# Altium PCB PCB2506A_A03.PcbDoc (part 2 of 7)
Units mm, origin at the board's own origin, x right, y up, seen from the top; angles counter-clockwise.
Board outline 115 x 60 mm, 6 copper layers (Top Layer, Signal Layer 2, Signal Layer 3, Signal Layer 4, Signal Layer 5, Bottom Layer), stack 1.555 mm thick; 376 components, 290 nets, 1297 pads, 901 vias.
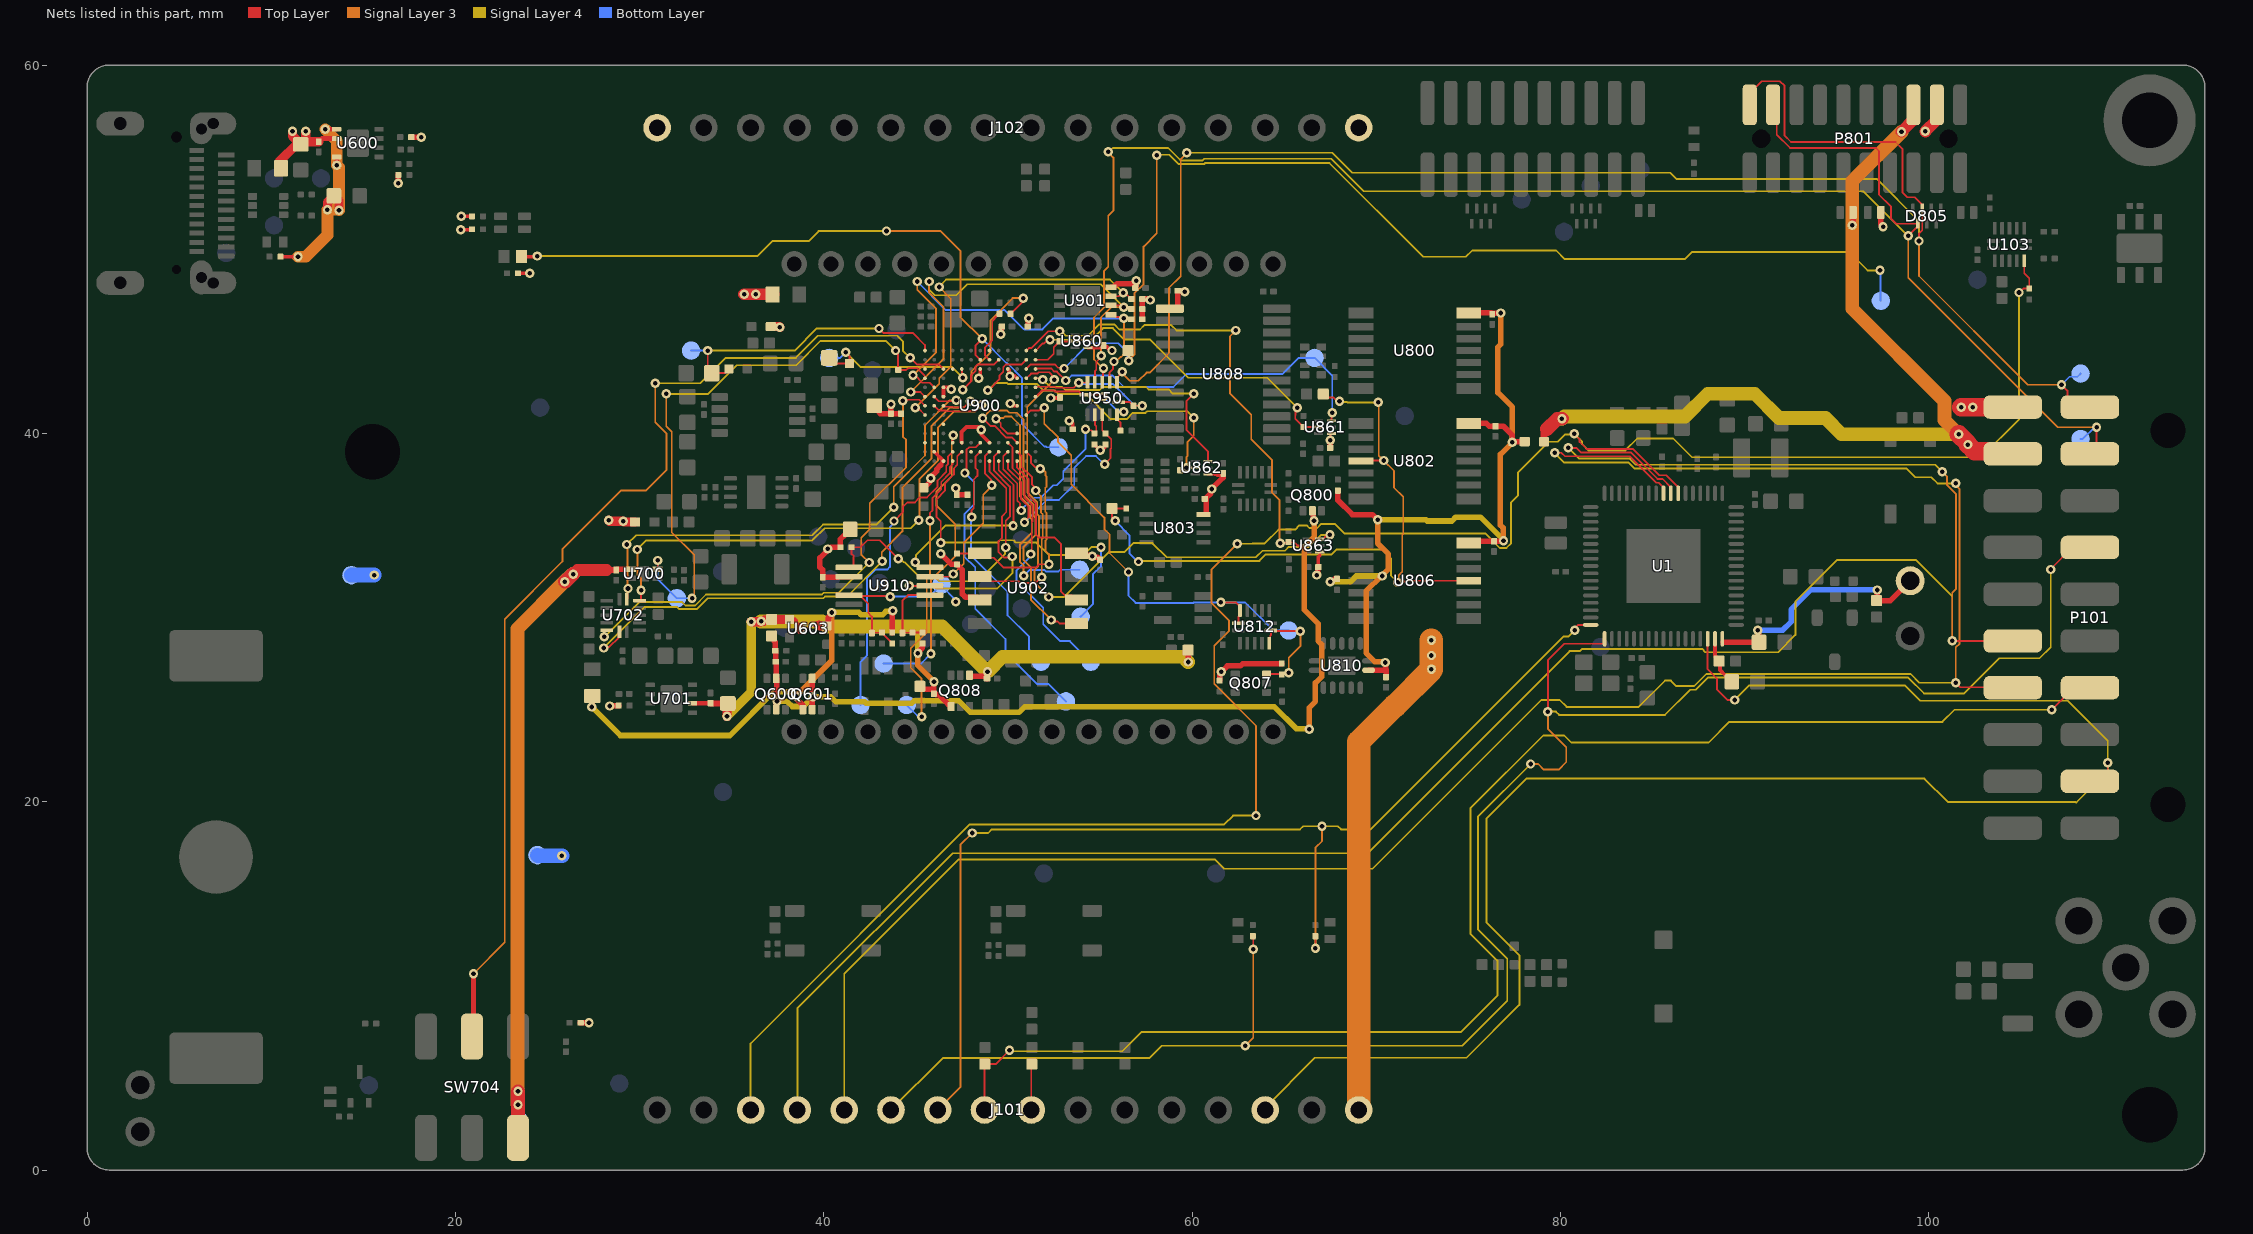
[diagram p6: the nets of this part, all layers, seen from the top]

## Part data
LED900: library part Yellow
LED901: library part Blue

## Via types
v1: diameter 0.508, hole 0.25, Top Layer to Bottom Layer, tented both sides, 901 vias

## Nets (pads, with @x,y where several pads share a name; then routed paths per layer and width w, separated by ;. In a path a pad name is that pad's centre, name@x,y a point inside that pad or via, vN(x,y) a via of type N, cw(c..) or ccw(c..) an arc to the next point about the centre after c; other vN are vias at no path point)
3V3: C607.1 C807.1 C808.1 C860.1 C862.1 C864.1 C866.1 C907.1 C908.1 C909.1 C910.1 C911.1 C914.1 C921.1 C922.1 C924.1 C925.1 C926.1 C927.1 C951.1 D807.1 J101.16 J102.16 L704.1 L900.1 P101.20 P801.3 R601.2 R793.2 R838.2 R840.2 R903.1 R906.2 R907.1 R908.1 R909.1 R912.1 R919.1 R920.1 R951.1 R952.1 R982.1 TPJ600.1 TPJ950.1 U600.1 U600.4 U803.8 U808.1 U860.1 U861.1 U862.1 U863.1 U900.C6 U900.C9 U900.G3 U900.H11 U900.J11 U900.K3 U900.L4 U900.L7 U901.8 U902.3 U902.8 U910.2 | length 92.6
  Top Layer w0.1: v1(67.513,39.624) 67.513,39.968 67.538,39.993 U861.1@67.573,39.993
  Top Layer w0.15: U862.1@60.873,37.785 61.239,37.785 ; 66.936,33.373 U863.1@66.936,33.563
  Top Layer w0.2: R903.1@10.5,49.6 v1(11.45,49.6) ; v1(20.295,51.054) R919.1@20.901,51.054 ; v1(20.32,51.791) 20.852,51.791 20.877,51.765 R920.1@20.901,51.789 ; R912.1@23.401,48.7 23.418,48.717 23.444,48.692 v1(24.028,48.692) ; U900.H11@46.5,42 U900.J11@46.5,42.5 46.825,42.5 v1(46.925,42.4) ; U900.C9@47.5,39.5 47.482,39.518 47.482,40.083 47.749,40.35 48.425,40.35 48.55,40.225 v1@48.55,40.075 ; v1(48.425,43) 48.45,43 48.5,43.05 U900.L7@48.5,43.5 ; v1(48.55,40.2) v1@48.55,40.075 ; U900.C6@49,39.5 48.525,39.975 48.55,40 v1@48.55,40.075 ; U900.L4@50,43.5 50.058,43.442 50.058,43.165 v1(50.112,43.112) ; v1(50.125,41.625) 50.25,41.5 U900.G3@50.5,41.5 ; v1@50.125,43.125 50.375,43.125 U900.K3@50.5,43 ; v1(52.325,41.925) 52.325,41.9 52.4,41.825 52.5,41.925 C911.1@52.825,41.925 ; v1(53.336,40.692) 53.336,40.714 53.325,40.725 53.35,40.725 53.525,40.55 C909.1@53.525,40.225 ; U860.1@54.35,44.65 55.023,44.65 55.068,44.695 55.14,44.695 C862.1@55.2,44.755 ; R951.1@54.7,39.4 54.7,39.39 54.94,39.15 v1@55.051,39.15 ; v1(55.021,39.091) 55.079,39.15 55.178,39.15 55.26,39.233 55.26,39.36 R952.1@55.3,39.4 ; C862.1@55.2,44.775 C862.1@55.2,44.755 ; v1(55.651,44.502) 55.573,44.502 55.38,44.695 55.26,44.695 C862.1@55.2,44.755 ; 61.239,37.785 61.392,37.785 ; C866.1@66.857,32.745 66.857,33.294 66.936,33.373
  Top Layer w0.25: v1@13.038,56.513 U600.1@13.55,56.513 ; U600.4@13.55,55.013 13.557,55.013 13.557,54.566 v1(13.564,54.559)
  Top Layer w0.3: v1(12.929,56.515) 13.036,56.515 v1@13.038,56.513 ; v1(16.891,53.594) 16.896,53.599 16.896,54.031 R601.2@16.9,54.035 ; R793.2@26.79,8 27.253,8 v1(27.254,8.001) ; U910.2@41.374,32.22 40.799,32.22 40.774,32.195 C922.1@39.946,32.195 39.936,32.205 39.936,32.595 39.794,32.737 39.794,33.239 40.226,33.671 v1(40.226,33.727) 40.282,33.727 40.376,33.821 R982.1@40.906,33.821 40.906,34.265 41.082,34.44 41.107,34.44 41.434,34.767 C921.1@41.434,34.792 ; C907.1@42.75,41.4 43.075,41.075 C924.1@43.65,41.075 ; v1(43.65,41.575) C924.1@43.65,41.075 ; C925.1@44.2,41.075 C924.1@43.65,41.075 ; v1@46.33,33.435 v1(46.357,33.463) 46.918,32.902 47.234,32.902 47.244,32.892 R906.2@47.244,32.882 47.244,32.872 47.531,32.585 47.531,31.28 47.707,31.104 48.322,31.104 U902.3@48.472,30.954 ; v1(47.175,37.033) 47.175,36.977 47.215,36.937 47.215,36.685 C927.1@47.225,36.675 C926.1@47.808,36.675 ; v1(49.612,45.383) 49.645,45.416 C910.1@49.645,45.757 ; C908.1@51.075,45.8 51.093,45.8 51.103,45.81 51.103,46.226 v1(51.13,46.253) ; v1(54.585,33.325) 54.624,33.285 54.866,33.285 54.983,33.169 55.003,33.169 55.013,33.159 C914.1@55.013,33.139 ; U901.8@55.6,47.95 55.75,47.95 55.933,48.133 56.842,48.133 C951.1@56.958,48.017 ; R908.1@57.3,46.2 R907.1@57.3,46.75 R909.1@57.3,47.3 57.622,47.3 57.678,47.244 v1(57.734,47.244) ; U808.1@58.8,46.775 59.15,46.775 59.225,46.85 C808.1@59.225,47.75 59.235,47.74 59.51,47.74 59.518,47.732 59.574,47.732 v1(59.614,47.693) ; C807.1@60.725,36.455 v1@61.022,36.751 ; U803.8@60.783,35.624 C807.1@60.783,36.378 ; v1(61.062,36.982) 61.685,37.606 C860.1@61.685,37.795 ; 61.392,37.785 61.47,37.785 61.48,37.795 C860.1@61.685,37.795 ; R838.2@61.5,26.587 61.51,26.597 61.51,26.91 61.595,26.995 v1(61.595,27.051) 61.919,27.375 62.63,27.375 62.76,27.505 R840.2@64.87,27.505 ; C860.1@61.695,37.805 C860.1@61.685,37.795 ; v1(66.777,32.309) 66.777,32.365 66.827,32.415 66.827,32.735 66.837,32.745 C866.1@66.857,32.745 ; C864.1@67.5,39.214 67.503,39.214 67.513,39.224 v1(67.513,39.624) ; D807.1@97.4,52 97.4,51.35 v1(97.525,51.225)
  Top Layer w0.35: U902.8@53.722,33.494 53.847,33.369 54.498,33.369 54.542,33.325 v1(54.585,33.325)
  Top Layer w0.5: v1(13.05,52.15) 13.05,52.55 C607.1@13.4,52.9 13.675,52.625 v1(13.675,52.125) ; L704.1@37.125,45.8 37.586,45.8 37.615,45.771 v1(37.617,45.771)
  Top Layer w0.635: v1(35.675,47.55) v1(36.3,47.55) L900.1@37.225,47.55 L900.1@37.285,47.55 ; v1(99.825,56.4) 100.445,57.02 P801.3@100.445,57.841 ; v1(102.387,41.427) 102.39,41.43 P101.20@104.57,41.43
  Top Layer w1: v1(101.778,41.427) v1(102.387,41.427) 104.567,41.427 P101.20@104.57,41.43
  Signal Layer 3 w0.635: v1(11.45,49.6) 11.881,49.6 13.05,50.769 v1(13.05,52.15) 13.65,52.15 v1(13.675,52.125) 13.675,54.448 v1(13.564,54.559) 13.564,55.88 v1(12.929,56.515)
  Signal Layer 3 w1.27: J101.16@69.05,3.262 69.05,23.254 71.015,25.218 71.035,25.218 73,27.183 v1(73,27.203) v1(73,27.94) v1(73,28.778)
  Bottom Layer w0.8: TPJ600.1@14.353,32.302 14.36,32.309 v1(15.596,32.309) ; TPJ950.1@24.452,17.1 24.484,17.069 v1(25.781,17.069)
  other v1: 56.974,48.285
3V6_SW: C608.1 L702.1 Q601.1 R639.2 U603.B1 | length 26
  Top Layer w0.2: U603.B1@39.35,29.6 39.735,29.6
  Top Layer w0.3: v1(27.407,25.146) 27.419,25.159 27.419,25.743 L702.1@27.407,25.756 ; v1(38.506,25.73) 38.546,25.69 38.546,25.563 38.869,25.24 Q601.1@38.869,25.09 ; C608.1@40.169,29.55 40.235,29.616 40.235,29.991 40.397,30.153 40.397,30.337 v1@40.411,30.351 ; R639.2@43.719,29.19 43.719,30.337 v1(43.755,30.373)
  Top Layer w0.5: 39.735,29.6 39.785,29.55 C608.1@40.169,29.55
  Signal Layer 3 w0.3: v1(38.506,25.73) 40.437,27.661 v1(40.437,30.277)
  Signal Layer 4 w0.3: v1(27.407,25.146) 28.956,23.597 34.9,23.597 37.287,25.984 38.196,25.984 38.45,25.73 v1(38.506,25.73) ; v1(40.437,30.277) 41.906,30.277 42.032,30.151 43.197,30.151 43.379,30.334 43.715,30.334 v1(43.755,30.373)
3V6_SW_SENSE: C641.1 R639.1 R640.2 TP923.1 U910.4 | length 10.3
  Top Layer w0.1: U910.4@41.374,31.22 41.414,31.18 U910.4@41.989,31.18 ; v1(43.612,31.14) 43.572,31.18 U910.4@41.989,31.18 ; R639.1@43.719,28.59 43.719,28.6 43.279,29.04 43.279,29.08 R640.2@43.169,29.19 43.157,29.178 42.632,29.178 C641.1@42.619,29.165 42.619,30.054 42.418,30.255 42.418,30.751 U910.4@41.989,31.18
  Bottom Layer w0.1: v1(43.612,31.14) 45.74,31.14 TP923.1@46.4,31.8 46.4,31.714 47.168,30.947 v1(47.168,30.861)
5V: C600.1 C609.1 C611.1 C673.1 C674.1 C702.1 C703.1 C901.1 D806.1 J102.1 L600.2 L700.1 L800.1 P101.18 P801.5 Q808.1 Q808.4 R600.2 R622.2 R633.2 R681.2 R690.2 R700.2 U600.2 U603.A2 U603.B2 U701.2 U900.A11 U900.B12 | length 108.6
  Top Layer w0.2: 38.424,29.82 38.557,29.687 ; U603.A2@38.95,29.2 38.944,29.206 38.674,29.206 38.557,29.323 38.557,29.687 ; U603.B2@38.95,29.6 38.944,29.606 38.638,29.606 38.557,29.687 ; U900.B12@46,39 U900.A11@46.5,38.5 46.4,38.4 46.4,38.325 46.35,38.275
  Top Layer w0.25: C600.1@12.576,55.834 12.576,55.854 12.735,56.013 U600.2@13.55,56.013 ; U701.2@32.878,25.342 33.847,25.342 C702.1@33.858,25.354
  Top Layer w0.3: R600.2@17.651,56.083 v1(18.136,56.083) ; v1(28.372,25.197) 28.402,25.197 28.376,25.222 R700.2@28.859,25.222 ; v1(45.116,28.062) 45.116,28.118 45.359,28.362 45.359,28.57 45.369,28.58 R633.2@45.369,28.59 ; R681.2@45.216,26.27 45.366,26.12 45.97,26.12 45.97,25.878 C674.1@45.98,25.868 ; C901.1@45.45,37.05 v1@45.768,37.368 ; v1(45.808,37.564) 45.808,37.62 46.126,37.938 46.126,38.052 46.35,38.275 ; 45.986,26.12 v1(45.986,26.517) ; C674.1@46.072,25.853 46.102,25.823 46.222,25.823 46.776,25.269 46.878,25.269 Q808.1@46.878,25.111 ; Q808.4@47.878,26.822 48.707,26.822 48.843,26.687 C673.1@48.863,26.687 ; C673.1@48.883,26.687 48.878,26.692 48.878,26.96 48.893,26.975 v1(48.893,27.056) ; v1(59.785,27.585) R690.2@59.785,28.228 ; 79.116,40.076 79.273,40.234 ; v1(95.85,51.3) 95.9,51.35 D806.1@95.9,52
  Top Layer w0.35: C702.1@33.858,25.354 33.868,25.354 33.887,25.335 C703.1@34.798,25.335 ; C609.1@38.144,29.9 38.219,29.825 38.419,29.825 38.424,29.82
  Top Layer w0.4: L800.1@79.116,39.551 79.116,40.076
  Top Layer w0.5: L600.2@10.465,54.4 10.465,54.79 11.375,55.7 C611.1@11.6,55.7 ; v1(11.15,56.4) 11.15,56.15 C611.1@11.6,55.7 ; v1(11.875,56.4) 11.875,55.975 C611.1@11.734,55.834 ; C600.1@12.576,55.834 C611.1@11.734,55.834 ; v1(28.321,35.281) v1(28.321,35.281) 28.372,35.231 29.107,35.231 v1(29.108,35.23) v1(29.108,35.23) 29.145,35.195 L700.1@29.758,35.195 ; v1(34.747,24.638) 34.749,24.64 34.749,25.286 C703.1@34.798,25.335 ; v1(36.068,29.769) 36.07,29.77 36.575,29.77 36.599,29.794 v1(36.601,29.794) 36.603,29.796 36.73,29.796 36.784,29.85 37.119,29.85 R622.2@37.169,29.9 C609.1@38.144,29.9 ; C611.1@11.6,55.7 C611.1@11.734,55.834
  Top Layer w0.635: v1(98.525,56.375) 99.175,57.025 P801.5@99.175,57.841
  Top Layer w0.75: 79.273,40.234 79.832,40.792 v1(80.086,40.792) ; P101.18@104.435,39.025 P101.18@104.57,38.89
  Top Layer w1: v1(101.625,39.954) 102.133,39.446 v1(102.133,39.395) 102.504,39.025 P101.18@104.435,39.025
  Signal Layer 3 w0.3: v1(45.116,28.062) 45.116,27.401 45.986,26.531 v1(45.986,26.517)
  Signal Layer 3 w0.75: v1(98.525,56.375) 95.85,53.7 v1(95.85,51.3) 95.85,46.771 100.863,41.758 100.863,40.716 v1(101.625,39.954) 102.133,39.446 v1(102.133,39.395)
  Signal Layer 4 w0.3: v1(45.116,28.062) 45.116,29.348
  Signal Layer 4 w0.5: v1(34.747,24.638) 36.068,25.959 v1(36.068,29.769) 36.093,29.794 v1(36.601,29.794)
  Signal Layer 4 w0.75: v1(36.601,29.794) 39.904,29.794 40.184,29.515 46.434,29.515 v1(48.893,27.056) 49.708,27.871 59.5,27.871 v1(59.785,27.585) ; v1(80.086,40.792) 80.215,40.921 86.774,40.921 88.006,42.153 90.559,42.153 91.875,40.837 94.392,40.837 95.275,39.954 v1(101.625,39.954) 102.133,39.446 v1(102.133,39.395)
5V_DH_SW: C803.1 C805.1 C809.1 C827.1 L800.2 R807.1 R808.1 U800.14 U802.14 U806.14 U810.14 | length 45.4
  Top Layer w0.3: v1(67.502,31.937) 67.542,31.977 67.624,31.977 67.733,32.086 67.866,32.086 67.876,32.096 R808.1@67.876,32.106 ; R807.1@67.92,36.894 67.92,36.372 68.707,35.585 69.799,35.585 70.066,35.318 v1(70.079,35.318) ; U810.14@69.585,27.143 70.418,27.143 ; v1(70.492,27.56) 70.531,27.52 70.531,27.16 70.535,27.156 C827.1@70.535,26.768 ; U806.14@75.025,34.05 75.113,34.138 C809.1@76.402,34.138 76.402,34.145 76.412,34.155 76.895,34.155 v1(76.911,34.171) ; U802.14@75.025,40.55 75.982,40.55 76.133,40.398 76.471,40.398 C805.1@76.479,40.391 76.906,40.391 77.382,39.916 77.382,39.527 v1(77.385,39.523) 77.399,39.537 78.052,39.537 L800.2@78.066,39.551 ; U800.14@75.025,46.55 76.237,46.55 76.252,46.535 76.753,46.535 v1(76.758,46.541)
  Signal Layer 3 w0.3: v1(70.079,35.318) 70.079,34.036 70.663,33.452 70.663,32.644 70.333,32.314 v1(70.333,32.258) 70.276,32.258 69.452,31.434 69.452,28.079 69.931,27.6 70.452,27.6 v1(70.492,27.56) ; v1(76.758,46.541) 76.758,44.84 76.606,44.688 76.606,42.215 77.394,41.427 v1@77.394,39.6 ; v1(76.911,34.171) 76.889,34.193 76.889,34.875 76.739,35.025 76.739,38.864 77.394,39.519 v1@77.394,39.523
  Signal Layer 4 w0.3: v1(67.502,31.937) 68.595,31.937 68.916,32.258 v1(70.333,32.258) ; v1(70.079,35.318) 72.69,35.318 72.764,35.245 74.105,35.245 74.319,35.458 75.661,35.458 76.911,34.208 v1(76.911,34.171)
5V_SENSE: C635.1 R633.1 R634.2 U910.7 | length 4.5
  Top Layer w0.1: R633.1@45.369,29.19 R634.2@44.819,29.19 44.807,29.178 44.282,29.178 C635.1@44.269,29.165 44.269,30.909 44.581,31.22 U910.7@45.774,31.22
5V_SW: C610.1 Q600.2 Q600.5 Q601.2 Q601.5 Q800.5 R622.1 R623.2 | length 48.9
  Top Layer w0.3: R622.1@37.254,28.916 37.319,28.85 37.319,28.724 37.369,28.674 R623.2@37.369,28.2 37.372,28.2 37.382,28.19 37.382,27.61 37.392,27.6 37.409,27.6 37.419,27.59 Q600.5@37.419,26.7 37.442,26.677 37.442,25.488 v1(37.465,25.465) ; Q600.2@37.42,25.09 37.43,25.1 v1@37.43,25.481 ; Q601.2@39.369,25.09 v1@39.369,25.653 ; v1@39.369,25.516 39.381,25.528 39.381,25.665 v1(39.421,25.705) 39.369,25.756 39.381,25.768 39.381,25.801 39.369,25.813 Q601.5@39.369,26.7 ; Q800.5@66.533,35.8 66.571,35.762 66.571,35.365 66.624,35.311 v1(66.624,35.255)
  Signal Layer 3 w0.3: v1(66.37,23.927) 66.37,25.113 66.701,25.444 66.701,26.449 67.034,26.783 67.034,28.546 66.845,28.735 66.845,29.675 66.084,30.436 66.084,33.844 66.624,34.384 v1(66.624,35.255)
  Signal Layer 4 w0.3: v1(37.465,25.465) 37.478,25.452 38.014,25.452 38.294,25.171 38.887,25.171 v1(39.421,25.705) 40.379,25.705 40.658,25.426 42.222,25.426 42.303,25.345 44.769,25.345 44.904,25.48 47.337,25.48 47.965,24.852 50.599,24.852 50.918,25.171 64.458,25.171 65.666,23.963 66.334,23.963 v1(66.37,23.927)
#RESET: R805.2 R809.1 R810.2 U802.4 U806.11 | length 38.7
  Top Layer w0.1: v1(55.825,35.25) 55.65,35.425 R810.2@55.65,35.925 R809.1@56.425,35.925 ; R805.2@67.126,42.139 67.316,41.949 67.694,41.949 67.897,41.746 v1(68.008,41.746) ; U802.4@69.175,38.5 69.202,38.527 v1(70.405,38.527) ; v1(71.171,31.906) 71.215,31.95 71.575,31.95 71.625,32 U806.11@75.025,32
  Signal Layer 3 w0.1: v1(70.117,41.686) 70.142,41.66 70.142,38.79 v1(70.405,38.527) ; v1@70.417,38.514 70.968,37.963 70.968,37.059 71.467,36.559 71.467,34.555 71.414,34.502 71.414,32.497 71.226,32.31 71.226,31.961 v1(71.171,31.906)
  Signal Layer 4 w0.1: v1(57.093,33.042) 57.125,33.074 63.656,33.074 64.011,33.43 65.26,33.43 65.262,33.432 67.578,33.432 67.838,33.692 70.321,33.692 70.804,33.209 70.804,32.272 v1(71.171,31.906) ; v1(68.008,41.746) 68.048,41.706 68.412,41.706 68.432,41.686 v1(70.117,41.686)
  Bottom Layer w0.1: v1(55.825,35.25) 56.6,34.475 56.6,33.5 57.058,33.042 v1(57.093,33.042)
ADC_SMA_IN: C130.1 R129.2 U1.33 | length 2.7
  Top Layer w0.2: U1.33@88.4,28.85 88.4,27.955 88.423,27.931 88.423,27.838 88.669,27.592 88.669,27.155 88.984,26.84 89.009,26.84 89.309,26.54 C130.1@89.309,26.515
ADC_VREF: C117.1 R116.1 TPH101.1 U1.34 | length 13.5
  Top Layer w0.1: U1.34@88.798,29.007 88.8,29.005 U1.34@88.8,28.85 88.8,28.715 U1.34@88.846,28.668
  Top Layer w0.3: U1.34@88.846,28.668 90.692,28.668 C117.1@90.791,28.668 ; C117.1@90.692,28.798 90.76,28.866 90.76,29.28 v1(90.729,29.312) ; v1(97.2,31.5) 97.2,30.95 R116.1@97.175,30.925 97.925,30.925 TPH101.1@99,32
  Bottom Layer w0.3: v1(90.729,29.312) 92.07,29.312 92.528,29.77 92.528,30.438 93.59,31.5 v1(97.2,31.5)
ADC_VREF_ENABLE: J101.3 R112.1 U1.58 U103.5 | length 119.7
  Top Layer w0.1: v1(80.755,39.975) 81.04,39.689 81.04,39.542 81.42,39.162 83.93,39.162 85.366,37.725 85.75,37.725 86.4,37.075 U1.58@86.4,36.75 ; v1(104.909,47.655) 104.937,47.655 105.156,47.874 R112.1@105.461,47.874 105.461,48.415 105.188,48.688 U103.5@105.188,49.366
  Signal Layer 3 w0.1: v1(62.459,34.011) 61.062,32.614 61.062,30.776 62.013,29.824 62.013,29.273 61.202,28.462 61.202,26.403 63.475,24.13 v1(63.475,19.249)
  Signal Layer 4 w0.1: J101.3@36.03,3.262 36.03,6.871 47.93,18.771 61.751,18.771 62.229,19.249 v1(63.475,19.249) ; v1(62.459,34.011) 63.286,34.011 63.305,34.03 63.943,34.03 64.695,34.781 65.607,34.781 65.83,35.004 66.238,35.004 66.38,34.862 66.787,34.862 67.011,35.086 67.759,35.086 68.272,34.573 75.921,34.573 76.715,33.778 77.074,33.778 77.324,34.028 77.324,36.259 77.707,36.643 77.707,37.893 79.362,39.548 79.871,39.548 80.27,39.946 80.726,39.946 v1(80.755,39.975) ; v1@80.747,39.954 80.775,39.954 81.178,39.551 81.178,39.425 81.523,39.08 83.53,39.08 84.176,39.726 86.131,39.726 87.149,38.708 102.843,38.708 104.909,40.774 v1(104.909,47.655)
AEM_5V_#ENABLE: U900.L10
AEM_CALIBRATE0: U702.13 U900.G11 | length 31.4
  Top Layer w0.1: v1(28.046,28.35) 28.104,28.407 28.356,28.407 28.861,28.912 28.861,29.184 U702.13@28.911,29.234 ; U900.G11@46.5,41.5 46.55,41.45 46.999,41.45 47.04,41.409 47.609,41.409 v1(47.952,41.752) 47.975,41.775 v1@48,41.775
  Signal Layer 3 w0.1: v1(43.17,33.05) 43.149,33.071 43.149,33.556 44.275,34.683 44.275,37.05 45.85,38.625 45.85,40.4 46.85,41.4 47.6,41.4 v1(47.952,41.752)
  Signal Layer 4 w0.1: v1(28.046,28.35) 30.264,30.568 32.038,30.568 32.149,30.457 33.096,30.457 33.691,31.053 39.982,31.053 40.076,31.146 41.266,31.146 v1(43.17,33.05)
AEM_CALIBRATE1: U702.5 U900.G12 | length 30
  Top Layer w0.1: U702.5@29.996,30.919 30.03,30.919 30.08,30.969 v1(30.08,31.49) ; U900.G12@46,41.5 46.25,41.25 46.604,41.25 46.652,41.202 48.227,41.202 v1(48.575,41.55)
  Signal Layer 3 w0.1: v1(29.881,33.699) 29.881,32.323 30.08,32.125 v1(30.08,31.49) ; v1(45.164,35.29) 45.206,35.332 45.206,37.531 46.2,38.525 46.2,40.3 47.093,41.193 48.218,41.193 v1(48.575,41.55)
  Signal Layer 4 w0.1: v1(29.881,33.699) 30.371,34.188 39.383,34.188 40.044,34.85 44.724,34.85 v1(45.164,35.29)
AEM_CALIBRATE2: U702.6 U900.H12 | length 27.1
  Top Layer w0.1: U702.6@29.311,31.004 29.341,31.033 29.341,31.551 v1(29.37,31.58) ; U900.H12@46,42 46.25,41.75 47.15,41.75 v1(47.202,41.802)
  Signal Layer 3 w0.1: v1(29.31,33.97) 29.34,33.94 29.34,31.61 v1(29.37,31.58) ; v1(43.8,36) 43.8,37.1 45.5,38.8 45.5,40.45 46.852,41.802 v1(47.202,41.802)
  Signal Layer 4 w0.1: v1(29.31,33.97) 29.808,34.468 39.379,34.468 39.962,35.05 42.85,35.05 v1(43.8,36)
AEM_CALIBRATE3: U702.12 U900.G13 | length 28.3
  Top Layer w0.1: v1(28.081,28.967) 28.081,29.269 28.131,29.319 U702.12@28.226,29.319 ; v1(44.3,41.775) 44.3,41.657 44.332,41.625 44.532,41.825 45.175,41.825 U900.G13@45.5,41.5
  Signal Layer 3 w0.1: v1(42.47,32.99) 42.037,33.423 42.037,34.342 42.5,34.805 42.5,36.2 44.475,38.175 44.475,39.656 44.3,39.831 v1(44.3,41.775)
  Signal Layer 4 w0.1: v1(28.081,28.967) 28.104,28.967 29.976,30.84 32.31,30.84 32.493,30.657 33.013,30.657 33.608,31.253 39.899,31.253 39.993,31.346 40.826,31.346 v1(42.47,32.99)
AEM_CURRENT_HIGH_GAIN: C720.1 R764.2 TP706.1 U900.N13 | length 16.2
  Top Layer w0.1: v1(33.7,44.5) 33.7,43.5 R764.2@33.925,43.275 34.625,43.275 C720.1@34.85,43.5 ; v1(43,45.7) 43.25,45.45 44.85,45.45 45.5,44.8 U900.N13@45.5,44.5
  Signal Layer 4 w0.1: v1(33.7,44.5) 38.429,44.5 39.629,45.7 v1(43,45.7)
  Bottom Layer w0.1: TP706.1@32.8,44.5 v1(33.7,44.5)
AEM_CURRENT_LOW_GAIN: C724.1 R768.2 TP707.1 U900.L9 | length 10.4
  Top Layer w0.1: R768.2@40.3,44.1 40.6,43.8 C724.1@41.4,43.8 41.4,44.2 v1(41.2,44.4) ; U900.L9@47.5,43.5 47.5,43.2 47.575,43.125 v1@47.552,43.102 ; v1(47.55,43.025) v1@47.55,43.1 ; v1@47.55,43.1 47.525,43.1 47.527,43.102 v1@47.552,43.102 ; v1@47.55,43.1 v1@47.552,43.102
  Signal Layer 4 w0.1: v1(41.2,44.4) 42,43.6 46.975,43.6 v1(47.55,43.025)
  Bottom Layer w0.1: TP707.1@40.3,44.1 40.9,44.1 v1(41.2,44.4)
AEM_SENSE_SELECT: U900.L13
AEM_SWITCH_POS: SW704.2 U900.L11 | length 58.7
  Top Layer w0.1: v1(44.7,44.1) 45.05,43.75 46.25,43.75 U900.L11@46.5,43.5
  Top Layer w0.25: SW704.2@20.9,7.25 20.98,7.33 v1(20.98,10.668)
  Signal Layer 3 w0.1: v1(20.98,10.668) 22.682,12.37 22.682,29.921 25.806,33.045 25.806,33.706 29.007,36.906 30.353,36.906 31.471,38.024 31.471,39.979 30.85,40.6 v1(30.85,42.725)
  Signal Layer 4 w0.1: v1(30.85,42.725) 33.3,42.725 34.675,44.1 38.487,44.1 39.687,45.3 44,45.3 44.3,45 44.3,44.5 v1(44.7,44.1)
AEM_VMCU: C708.1 SW704.4 TP709.1 U700.1 | length 38
  Top Layer w0.3: 28.213,32.583 C708.1@28.733,32.583 ; C708.1@28.764,32.634 U700.1@29.533,32.634
  Top Layer w0.635: v1(26.391,32.36) 26.614,32.583 28.213,32.583
  Top Layer w0.75: SW704.4@23.4,1.75 v1(23.4,3.55) v1(23.4,4.275) ; v1(25.933,31.953) 25.984,31.953 v1(26.391,32.36)
  Signal Layer 3 w0.75: v1(23.4,3.55) 23.375,3.575 23.375,29.395 v1(25.933,31.953) 26.289,32.309 26.34,32.309 v1(26.391,32.36)
  Bottom Layer w0.635: v1(23.4,4.275) v1(23.4,3.55) 23.425,3.525 TP709.1@23.425,2.725
AEM_VMCU_ENABLE: R763.2 TP715.1 U700.4 U900.K13 | length 32.3
  Top Layer w0.1: U700.4@30.983,32.634 v1(30.983,33.103) ; v1(43.9,44.5) 44.025,44.375 44.025,43.475 R763.2@44.05,43.45 44.485,43.45 44.578,43.543 45.078,43.543 45.484,43.137 45.484,43.016 U900.K13@45.5,43
  Signal Layer 3 w0.1: v1(31.45,42.15) 31.45,40.381 31.75,40.081 31.75,34.62 32.969,33.401 32.969,31.28 32.85,31.16 v1(32.85,31.05)
  Signal Layer 4 w0.1: v1(31.45,42.15) 33.725,42.15 35.275,43.7 38.5,43.7 39.825,45.025 43.375,45.025 v1(43.9,44.5)
  Bottom Layer w0.1: v1(30.983,33.103) 30.983,32.092 TP715.1@32.025,31.05 v1(32.85,31.05)
AIN1: J101.14 P101.3 U1.32 | length 92.4
  Top Layer w0.1: U1.32@88,28.85 88,27.192 88.5,26.693 88.5,26.099 89.072,25.527 v1(89.462,25.527) ; P101.3@108.76,21.11 109.385,21.11 109.725,21.45 v1(109.725,22.125)
  Signal Layer 4 w0.1: J101.14@63.97,3.262 63.97,3.391 66.675,6.096 74.905,6.096 77.775,8.966 77.775,11.659 75.994,13.44 75.994,19.094 78.16,21.26 99.771,21.26 101.041,19.99 107.975,19.99 108.004,19.961 108.03,19.961 109.725,21.656 v1(109.725,22.125) 109.725,23.304 107.544,25.485 99.534,25.485 98.704,26.314 90.25,26.314 v1(89.462,25.527)
BC_ADC_SPI_CIPO: U900.B6 U910.9 | length 9.1
  Top Layer w0.1: U910.9@45.774,32.22 46.78,32.22 46.928,32.367 v1(47.038,32.367) ; U900.B6@49,39 48.75,38.75 48.75,37.831 49.079,37.502 49.079,37.238 v1(49.132,37.184)
  Signal Layer 3 w0.1: v1(47.038,32.367) 47.6,32.929 47.6,34.061 48.666,35.128 48.666,36.668 49.132,37.134 v1(49.132,37.184)
BC_ADC_SPI_COPI: U900.A6 U910.8 | length 14.4
  Top Layer w0.1: v1(44.65,31.725) 44.652,31.722 45.762,31.722 U910.8@45.765,31.72 ; U900.A6@49,38.5 49,37.944 49.911,37.033 49.911,35.733 49.682,35.504 49.682,34.337 49.495,34.149 49.495,33.551 49.789,33.257 50.189,33.257 v1(50.246,33.314)
  Signal Layer 4 w0.1: v1(44.65,31.725) 45.968,31.725 46.118,31.575 49.41,31.575 50.246,32.411 v1(50.246,33.314)
BC_ADC_SPI_CS: R982.2 U900.B5 U910.1 | length 17.5
  Top Layer w0.1: U910.1@41.374,32.72 41.523,32.72 41.623,32.82 41.623,33.358 41.506,33.475 R982.2@41.506,33.821 41.993,33.821 42.376,34.203 43.043,34.203 44.047,33.199 v1(44.047,33.197) ; U900.B5@49.5,39 49.25,38.75 49.25,37.977 50.111,37.116 50.111,35.476 49.888,35.253 v1(49.888,33.805)
  Signal Layer 4 w0.1: v1(44.047,33.197) 44.157,33.197 44.351,33.003 44.401,33.003 45.229,32.175 46.084,32.175 46.284,31.975 48.358,31.975 49.852,33.469 49.852,33.77 v1(49.888,33.805)
BC_ADC_SPI_SCLK: U900.A5 U910.10 | length 11.2
  Top Layer w0.1: v1(44.961,32.998) 44.961,32.957 45.128,32.791 45.703,32.791 U910.10@45.774,32.72 ; U900.A5@49.5,38.5 49.5,38.01 50.311,37.199 50.311,35.021 v1(50.281,34.991)
  Signal Layer 4 w0.1: v1(44.961,32.998) 45.018,33.055 45.018,33.402 46.607,34.991 v1(50.281,34.991)
BC_BUTTON_ENABLE: R981.1 U900.H1 U950.6 U950.12 | length 6.8
  Top Layer w0.1: U900.H1@51.5,42 51.832,42.332 52.474,42.332 52.526,42.28 53.845,42.28 54.025,42.1 U950.6@54.24,42.1 55.075,42.1 v1(55.175,42) ; R981.1@56.121,40.149 56.121,40.579 55.925,40.775 U950.12@55.925,41.015 55.925,41.123 55.975,41.173 v1(56.286,41.173)
  Bottom Layer w0.1: v1(55.175,42) 55.924,41.251 56.208,41.251 v1(56.286,41.173)
BC_DAC_OUT: U900.N6
BC_DBG_#RESET: LED903.1 TPJ956.1 U900.M7 | length 39.6
  Top Layer w0.1: U900.M7@48.5,44 48.25,44.25 48.25,44.782 v1(48.602,45.134)
  Top Layer w0.2: LED903.1@23.576,49.6 24.403,49.6 v1(24.435,49.632)
  Signal Layer 3 w0.1: v1(43.409,50.99) 46.343,50.99 47.425,49.908 47.425,46.311 v1(48.602,45.134)
  Signal Layer 4 w0.1: v1(24.435,49.632) 36.398,49.632 37.211,50.444 39.176,50.444 39.721,50.99 v1(43.409,50.99)
  Bottom Layer w0.1: v1(48.602,45.134) 49.911,43.825 49.954,43.825 50.775,43.004 50.775,40.5 51.986,39.289 52.084,39.289 52.122,39.251 TPJ956.1@52.753,39.251
BC_DBG_TCK_SWCLK: TPJ954.1 U900.C10 | length 16.6
  Top Layer w0.1: U900.C10@47,39.5 47,39.775 46.95,39.825 46.95,39.85 47,39.9 v1(47.025,39.9) ; v1@47.125,39.852 v1@47.125,39.9
  Signal Layer 3 w0.1: v1(45.822,28.042) 45.822,32.022 47.142,33.342 47.142,35.058 46.132,36.068 46.132,36.849 46.954,37.671 46.954,39.829 v1(47.025,39.9)
  Bottom Layer w0.1: TPJ954.1@43.253,27.501 45.281,27.501 v1(45.822,28.042) ; v1@46.957,39.832 v1(47.025,39.9)
BC_DBG_TDO_SWO: TPJ955.1 U900.A10 | length 16.2
  Top Layer w0.1: v1(45.771,35.255) 45.771,35.688 45.911,35.828 45.911,36.499 46.382,36.971 46.382,37.362 46.85,37.829 46.85,38.17 47,38.32 U900.A10@47,38.5
  Signal Layer 3 w0.1: v1(45.314,24.613) 45.314,26.685 44.723,27.275 44.723,28.34 45.593,29.21 45.593,32.182 45.771,32.36 v1(45.771,35.255)
  Bottom Layer w0.1: TPJ955.1@44.503,25.251 45.063,24.691 45.236,24.691 v1(45.314,24.613)
BC_DBG_TMS_SWDIO: TPJ953.1 U900.B10 | length 16.7
  Top Layer w0.1: v1(43.815,35.243) 44.3,35.728 44.3,36.009 44.541,36.25 44.929,36.25 44.95,36.25 45.225,36.525 45.608,36.525 46.182,37.099 46.182,37.444 46.65,37.912 46.65,38.253 46.75,38.353 46.75,38.75 U900.B10@47,39
  Bottom Layer w0.1: TPJ953.1@42.001,25.251 42.001,26.16 42.001,27.602 42.354,27.955 42.354,32.148 42.807,32.602 43.443,32.602 43.596,32.754 43.596,34.913 43.815,35.132 v1(43.815,35.243)
BC_DISP_COM: U900.E11
BC_DISP_PWR_ENABLE: U900.D12
BC_DISP_SPI_COPI: U900.B8
BC_DISP_SPI_CS: U900.C12
BC_DISP_SPI_SCLK: U900.C13
BC_I2C_EXP_ENABLE: R950.1 U900.J1 U950.5 U950.13 | length 8.4
  Top Layer w0.1: U900.J1@51.5,42.5 51.5,42.532 52.556,42.532 52.608,42.48 53.58,42.48 v1(53.85,42.75) 54.29,42.75 U950.5@54.325,42.785 ; U950.13@56.01,41.7 56.625,41.7 56.873,41.452 56.922,41.502 57.296,41.502 v1(57.298,41.504)
  Bottom Layer w0.1: v1(53.85,42.75) 53.921,42.679 55.721,42.679 56.901,41.499 57.293,41.499 v1(57.298,41.504)
BC_I2C_EXP_SCL: D805.5 P101.17 P801.17 TPJ651.1 U950.3 | length 91.5
  Top Layer w0.1: U950.3@55.125,42.785 55.159,42.819 55.159,43.502 v1(55.193,43.536) ; P801.17@91.555,57.841 91.75,57.647 91.75,56.225 92.475,55.5 97.15,55.5 97.3,55.35 97.3,52.975 97.95,52.325 97.95,51.675 98.24,51.385 D805.5@99.4,51.385 99.4,51.25 v1(98.892,50.742) ; P101.17@108.76,38.89 108.76,39.135 108.799,39.135 109.118,39.455 v1(109.118,40.335)
  Signal Layer 3 w0.1: v1(55.193,43.536) 55.163,43.536 54.906,43.792 54.675,44.022 54.675,46.294 55.217,46.836 55.217,48.815 55.449,49.047 55.449,51.813 55.729,52.092 55.729,54.981 55.442,55.267 v1(55.442,55.29) ; v1(98.892,50.742) 98.892,48.458 107.015,40.335 v1(109.118,40.335)
  Signal Layer 4 w0.1: v1(55.442,55.29) 55.496,55.29 55.705,55.499 58.702,55.499 59.375,54.826 60.571,54.826 60.659,54.915 67.564,54.915 69.328,53.151 96.46,53.151 98.869,50.742 v1(98.892,50.742)
  Bottom Layer w0.1: TPJ651.1@108.25,39.7 108.372,39.7 109.008,40.335 v1(109.118,40.335)
BC_I2C_EXP_SDA: D805.3 P101.19 P801.19 TPJ650.1 U950.1 | length 91.5
  Top Layer w0.1: U950.1@55.925,42.785 55.925,43.025 56.21,43.31 v1(56.21,43.358) ; P801.19@90.285,57.841 90.285,58.485 90.925,59.125 91.925,59.125 92.175,58.875 92.175,56.175 92.525,55.825 98.2,55.825 98.575,55.45 98.575,53.1 98.85,52.825 99.25,52.825 99.65,52.425 D805.3@99.65,52.215 99.65,51.025 99.475,50.85 v1(99.475,50.45) ; v1(107.213,42.647) 107.535,42.325 107.535,41.915 108.02,41.43 P101.19@108.76,41.43
  Signal Layer 3 w0.1: v1(56.21,43.358) 56.21,43.259 56.606,42.863 57.09,42.863 57.533,43.306 57.707,43.306 58.75,44.35 58.75,47.904 59.385,48.539 59.385,54.889 59.721,55.225 v1(59.721,55.243) ; v1(99.475,50.45) 99.475,48.55 105.378,42.647 v1(107.213,42.647)
  Signal Layer 4 w0.1: v1(59.721,55.243) 59.723,55.245 67.615,55.245 68.707,54.153 85.972,54.153 86.3,53.825 97.175,53.825 99.475,51.525 v1(99.475,50.45)
  Bottom Layer w0.1: v1(107.213,42.647) 107.647,43.081 108.083,43.081 TPJ650.1@108.25,43.248
BC_SPI_CIPO: U900.B3 U902.2 | length 11.1
  Top Layer w0.1: U902.2@48.472,32.224 48.722,31.974 50.594,31.974 50.693,31.875 51.495,31.875 51.802,32.182 v1(51.841,32.182) ; U900.B3@50.5,39 50.75,38.75 50.75,38.174 51.311,37.613 51.311,37.216 51.518,37.009 v1(51.518,36.899)
  Signal Layer 3 w0.1: v1(51.518,36.899) 51.518,36.878 51.793,36.603 51.793,35.706 51.897,35.602 51.897,34.313 51.839,34.255 51.839,33.556 51.841,33.553 v1@51.841,32.182
BC_SPI_COPI: U900.C3 U902.5 | length 18.5
  Top Layer w0.1: v1(48.625,40.825) 49.043,40.407 49.284,40.407 49.916,39.775 50.225,39.775 U900.C3@50.5,39.5 ; v1(52.349,29.87) 52.427,29.792 52.695,29.792 52.803,29.684 U902.5@53.722,29.684
  Signal Layer 3 w0.1: v1(48.625,40.825) 49.05,41.25 49.945,41.25 50.074,41.12 50.473,41.12 50.851,40.742 50.851,36.681 51.393,36.139 51.393,35.526 51.497,35.422 51.497,34.479 50.854,33.836 50.854,33.122 51.249,32.727 51.249,30.971 v1(52.349,29.87)
BC_SPI_CS: R906.1 U900.B2 U902.1 | length 12.3
  Top Layer w0.1: R906.1@47.244,33.482 48.461,33.482 U902.1@48.472,33.494 48.797,33.494 49.043,33.249 49.232,33.249 49.759,32.721 51.543,32.721 51.715,32.893 v1(52.234,32.893) ; U900.B2@51,39 51.25,38.75 51.25,38.396 51.485,38.162 51.681,38.162 v1(51.759,38.084)
  Signal Layer 3 w0.1: v1(51.759,38.084) 51.858,38.084 52.045,37.897 52.045,37.703 52.099,37.649 52.099,37.112 52.029,37.042 52.029,35.753 52.097,35.685 52.097,34.23 52.039,34.172 52.039,33.638 52.234,33.443 v1(52.234,32.893)
BC_SPI_SCLK: U900.A3 U902.6 | length 9.6
  Top Layer w0.1: U900.A3@50.5,38.5 50.5,38.141 51.111,37.53 51.111,36.602 51.528,36.185 51.528,35.141 51.528,34.496 51.683,34.341 52.544,34.341 52.883,34.002 52.883,31.42 53.099,31.204 53.472,31.204 U902.6@53.722,30.954
BC_TRACECLK: TPJ957.1 U900.B7 | length 13.3
  Top Layer w0.1: v1(48.031,35.458) 48.031,35.819 48.15,35.938 48.15,37.497 48.343,37.69 48.343,38.013 48.25,38.106 48.25,38.75 U900.B7@48.5,39
  Bottom Layer w0.1: v1(48.031,35.458) 48,35.427 48,33.369 49.979,31.391 49.979,30.121 51.15,28.95 51.15,28.248 TPJ957.1@51.799,27.599
BC_TRACED0: TPJ958.1 U900.C7 | length 17.7
  Top Layer w0.1: v1(47.668,37.853) 47.746,37.931 47.746,38.144 47.75,38.149 47.75,39.104 47.896,39.25 48.25,39.25 U900.C7@48.5,39.5
  Bottom Layer w0.1: v1@47.669,37.853 48.15,37.372 48.15,36.133 47.639,35.621 47.639,33.312 48.225,32.725 48.225,30.475 49.863,28.837 49.863,28.112 51.575,26.4 52.2,26.4 TPJ958.1@53.15,25.45
BC_TRACED1: TPJ959.1 U900.C4 | length 14.8
  Top Layer w0.1: U900.C4@50,39.5 50.25,39.25 50.25,38.108 50.911,37.447 50.911,36.519 51.328,36.102 51.328,35.224 51.297,35.193 51.297,33.499 v1(51.247,33.449)
  Bottom Layer w0.1: v1(51.247,33.449) 51.247,33.339 50.838,32.93 50.463,32.555 50.463,31.986 51.918,30.531 51.918,29.642 52.833,28.727 53.371,28.727 TPJ959.1@54.499,27.599
BC_TRACED2: TPJ960.1 U900.D3 | length 15.2
  Top Layer w0.1: v1(49.353,40.797) 49.61,40.54 49.61,40.364 49.974,40 U900.D3@50.5,40
  Signal Layer 3 w0.1: v1(49.353,40.797) 49.391,40.834 49.754,40.834 49.84,40.92 50.19,40.92 50.651,40.459 50.651,36.598 51.193,36.056 51.193,35.443 51.297,35.339 51.297,34.609 50.654,33.966 50.654,33.039 50.856,32.837 v1(50.856,32.268)
  Bottom Layer w0.1: v1(50.856,32.268) 50.856,32.269 51.161,32.575 52.004,32.575 52.078,32.501 52.732,32.501 52.83,32.598 TPJ960.1@53.899,32.598
BC_TRACED3: TPJ961.1 U900.B9 | length 19.1
  Top Layer w0.1: v1(46.357,34.071) 46.357,35.225 46.132,35.45 46.132,36.438 46.582,36.888 46.582,37.279 47.075,37.771 47.075,38.112 47.25,38.287 47.25,38.75 U900.B9@47.5,39
  Signal Layer 4 w0.1: v1(46.357,34.071) 48.324,34.071 48.328,34.075 49.434,34.075 49.557,34.198 50.311,34.198 50.434,34.075 51.549,34.075 52.222,33.401 54.105,33.401 54.529,33.825 v1(55.057,33.825)
  Bottom Layer w0.1: TPJ961.1@53.95,30.05 54.62,30.72 54.62,32.341 55.057,32.778 v1(55.057,33.825)
BC_UIF_BUTTON0: R951.2 U900.B4 U950.9 | length 11.6
  Top Layer w0.1: U900.B4@50,39 49.75,38.75 49.75,38.043 50.511,37.282 50.511,36.354 50.657,36.207 50.657,35.892 v1(50.735,35.814) ; v1(54.213,40.222) 54.266,40.169 54.531,40.169 54.58,40.12 54.59,40.12 54.7,40.01 R951.2@54.7,40 ; U950.9@54.725,41.015 54.725,40.475 54.8,40.4 54.8,40 R951.2@54.745,40.055
  Bottom Layer w0.1: v1(50.735,35.814) 50.735,35.866 51.376,36.506 51.776,36.506 52.459,37.189 52.665,37.189 53.009,37.534 53.009,37.947 54.213,39.151 v1(54.213,40.222)
BC_UIF_BUTTON1: R952.2 U900.A4 U950.10 | length 13.5
  Top Layer w0.1: U900.A4@50,38.5 50,38.076 50.711,37.365 50.711,36.436 51.128,36.019 51.128,35.439 50.904,35.215 v1(50.904,35.177) ; U950.10@55.125,41.015 55.125,40.175 R952.2@55.3,40 55.3,39.99 55.61,39.68 55.61,39.187 55.581,39.158 55.581,38.664 55.268,38.352 v1(55.268,38.329)
  Bottom Layer w0.1: v1(50.904,35.177) 52.113,36.386 52.767,36.386 53.601,37.22 53.601,38.132 54.244,38.775 54.781,38.775 55.227,38.329 v1(55.268,38.329)
BC_VCOM_CTS: U863.3 U900.K2 | length 33.1
  Top Layer w0.1: U900.K2@51,43 51.012,43 51.262,43.25 51.604,43.25 51.671,43.318 52.237,43.318 52.525,43.03 v1(52.525,42.925) ; v1@52.5,42.825 52.55,42.775 v1@52.575,42.8 ; U863.3@66.936,34.263 67.111,34.263 67.264,34.415 67.41,34.415 v1(67.488,34.493)
  Signal Layer 3 w0.1: 51.64,33.472 51.64,32.776 51.449,32.585 51.449,31.889 v1(52.222,31.115) ; 51.639,33.473 51.639,34.338 51.697,34.396 51.697,35.505 51.593,35.609 51.593,36.268 51.051,36.81 51.051,41.451 v1(52.525,42.925)
  Signal Layer 4 w0.1: v1(52.222,31.115) 53.035,31.115 55.477,33.557 56.313,33.557 56.804,34.048 57.849,34.048 58.623,33.274 63.471,33.274 63.826,33.63 65.049,33.63 65.259,33.839 66.351,33.839 67.005,34.493 v1(67.488,34.493)
BC_VCOM_CTS_DIR: R853.2 U863.5 U900.N2 | length 26.9
  Top Layer w0.1: U900.N2@51,44.5 51.027,44.5 51.172,44.645 51.291,44.645 51.396,44.75 52.197,45.55 v1(52.825,45.55) ; v1(64.784,34.032) 64.817,34.065 65.207,34.065 R853.2@65.24,34.098 65.248,34.09 65.55,34.09 65.707,33.933 ; 65.71,33.934 65.721,33.923 66.226,33.923 U863.5@66.236,33.913
  Signal Layer 3 w0.1: v1(62.382,45.593) 62.052,45.263 62.052,42.189 63.217,41.024 63.217,39.678 64.335,38.56 64.335,36.804 64.745,36.395 64.745,34.072 v1(64.784,34.032)
  Signal Layer 4 w0.1: v1(52.825,45.55) 52.9,45.55 53.148,45.302 54.352,45.302 54.968,45.918 55.784,45.918 56.058,45.644 57.175,45.644 57.412,45.88 58.87,45.88 59.157,45.593 v1(62.382,45.593)
BC_VCOM_ENABLE: Q807.3 R840.1 TP930.1 U812.5 U812.6 U812.12 U812.13 U900.F2 | length 31.6
  Top Layer w0.1: U900.F2@51,41 51.25,41.25 51.7,41.25 51.85,41.4 v1(51.975,41.4) ; v1(61.57,30.824) 62.381,30.824 62.53,30.675 62.55,30.675 62.55,30.655 62.6,30.605 U812.12@62.6,30.385 62.6,30.145 62.515,30.06 U812.13@62.515,29.7 ; Q807.3@64.022,26.938 64.838,26.938 R840.1@64.87,26.905 ; U812.5@64.2,28.615 64.25,28.665 64.25,29.015 64.285,29.05 U812.6@64.285,29.3 64.305,29.28 65.864,29.28 v1(65.884,29.26) ; R840.1@64.854,26.921 64.889,26.956 65.202,26.956 v1(65.253,27.007)
  Signal Layer 3 w0.1: v1(51.975,41.4) 51.975,40.537 52.724,39.787 52.724,39.528 53.442,38.811 53.442,37.236 55.245,35.433 55.245,34.798 55.518,34.525 55.518,33.506 v1(56.55,32.474) ; v1(65.253,27.007) 65.253,27.813 65.884,28.444 v1(65.884,29.26)
  Bottom Layer w0.1: v1(56.55,32.474) 56.55,31.182 56.933,30.798 60.072,30.798 60.097,30.824 v1(61.57,30.824) 62.877,30.824 64.401,29.3 TP930.1@65.25,29.3 65.27,29.28 65.864,29.28 v1(65.884,29.26)
BC_VCOM_RTS: U862.3 U900.K1 | length 13.4
  Top Layer w0.1: U900.K1@51.5,43 51.825,43 v1(51.9,42.925) ; v1(60.096,42.164) 59.704,41.771 59.704,40.169 60.873,39 U862.3@60.873,38.485
  Signal Layer 4 w0.1: v1(51.9,42.925) 52.3,42.525 52.799,42.525 52.804,42.52 52.949,42.52 53.112,42.357 54.976,42.357 55.14,42.52 57.508,42.52 57.636,42.393 58.725,42.393 58.953,42.164 v1(60.096,42.164)
BC_VCOM_RTS_DIR: R852.2 U862.5 U900.M2 | length 19.3
  Top Layer w0.1: v1(48.9,42.35) 48.956,42.35 49.54,42.935 49.54,43.14 49.75,43.35 49.75,43.604 49.896,43.75 50.75,43.75 U900.M2@51,44 ; R852.2@59.354,37.997 59.422,38.065 59.628,38.065 v1(59.696,38.133) v1(59.696,38.133) 60.172,38.134 U862.5@60.173,38.135
  Signal Layer 3 w0.1: v1(59.696,38.133) v1(59.696,38.133) 59.697,38.716 59.746,38.765 59.746,39.528 60.096,39.878 v1(60.096,40.843)
  Signal Layer 4 w0.1: v1(48.9,42.35) 48.956,42.35 49.349,42.743 49.943,42.743 50.011,42.675 51.594,42.675 51.944,42.325 52.55,42.325 52.725,42.15 54.225,42.15 55.594,40.781 56.449,40.781 56.779,41.111 57.465,41.111 57.558,41.204 59.736,41.204 v1(60.096,40.843)
BC_VCOM_RXD: R882.2 TPJ606.1 U900.L2 | length 63.5
  Top Layer w0.1: U900.L2@51,43.5 51.25,43.75 52.541,43.75 52.723,43.569 53.006,43.569 v1(53.05,43.525) ; R882.2@56.525,44.5 56.566,44.459 v1(56.566,43.942)
  Signal Layer 3 w0.1: v1(56.566,43.942) 56.566,43.974 56.871,44.279 56.871,47.603 57.367,48.099 57.367,50.142 58.088,50.863 v1(58.088,55.106)
  Signal Layer 4 w0.1: v1(58.088,55.106) 58.112,55.13 58.764,55.13 59.267,54.626 60.654,54.626 60.71,54.683 67.466,54.683 72.558,49.59 74.874,49.59 75.218,49.934 79.779,49.934 80.244,49.47 86.76,49.47 87.136,49.845 95.687,49.845 96.679,48.853 v1(97.358,48.853)
  Bottom Layer w0.1: v1(53.05,43.525) 54.42,44.895 56.005,44.895 56.504,44.396 56.504,44.004 v1(56.566,43.942) ; v1(97.358,48.853) 97.381,48.83 97.381,47.224 TPJ606.1@97.404,47.202
BC_VCOM_RXD_DIR: R850.2 U860.5 U900.M1 | length 2.6
  Top Layer w0.1: U900.M1@51.5,44 52.154,44 52.49,44.336 52.49,44.69 52.68,44.88 52.69,44.88 52.8,44.99 R850.2@52.8,45 U860.5@53.5,45
BC_VCOM_TXD: TPJ607.1 U861.3 U900.L1 | length 20.3
  Top Layer w0.1: U900.L1@51.5,43.5 51.518,43.518 52.367,43.518 52.528,43.357 52.662,43.357 53.144,42.875 v1(53.15,42.875) ; U861.3@67.573,40.693 67.573,41.08 v1(67.615,41.123)
  Bottom Layer w0.1: v1(53.15,42.875) 53.186,42.875 53.453,43.143 54.605,43.143 55.682,43.143 56.305,42.52 58.988,42.52 59.698,43.231 64.922,43.231 65.792,44.101 TPJ607.1@66.653,44.101 67.615,43.139 v1(67.615,41.123)
BC_VCOM_TXD_DIR: R851.2 U861.5 U900.N1 | length 18.6
  Top Layer w0.1: U900.N1@51.5,44.5 51.887,44.887 51.979,44.887 52.176,45.084 v1(52.286,45.084) ; v1@65.704,41.422 v1(65.704,41.403) 65.626,41.325 65.626,41.015 65.608,40.997 65.608,40.8 66.048,40.359 R851.2@66.048,40.349 66.052,40.346 66.869,40.346 U861.5@66.873,40.343
  Signal Layer 4 w0.1: v1(52.286,45.084) v1(52.286,45.084) 54.535,45.085 55.168,45.718 55.701,45.718 56.324,45.095 57.527,45.095 ; 57.528,45.094 57.728,45.094 59.797,43.025 64.082,43.025 v1(65.704,41.403)
BOARD_ID_SCL: R907.2 U900.H13 U901.6 U950.4 | length 26.2
  Top Layer w0.1: v1(44.725,42.25) 45.25,42.25 U900.H13@45.5,42 ; U950.4@54.725,42.785 54.725,43.374 54.8,43.449 54.8,43.877 55.068,44.146 v1(55.068,44.209) ; U901.6@55.6,46.95 56.09,46.95 56.185,46.854 v1(56.296,46.854) 56.348,46.802 56.648,46.802 R907.2@56.7,46.75
  Signal Layer 3 w0.1: v1(44.725,42.25) 46.5,44.025 46.5,46.875 45.725,47.65 v1(45.725,48.25) ; v1(55.068,44.209) 55.064,44.213 55.064,44.656 55.057,44.663 55.057,46.307 55.604,46.854 v1(56.296,46.854)
  Signal Layer 4 w0.1: v1(45.725,48.25) 45.725,47.8 46.025,47.5 47.2,47.5 47.8,48.1 55.05,48.1 v1(56.296,46.854)
BOARD_ID_SDA: R908.2 U900.J12 U901.5 U950.2 | length 25.1
  Top Layer w0.1: v1(44.85,43.15) 44.96,43.15 45.36,42.75 45.75,42.75 U900.J12@46,42.5 ; U950.2@55.525,42.785 55.525,43.312 55.714,43.501 55.714,43.854 v1(55.765,43.905) ; U901.5@55.6,46.45 55.75,46.45 55.875,46.325 56.216,46.325 56.317,46.223 56.677,46.223 R908.2@56.7,46.2
  Signal Layer 3 w0.1: v1(44.85,43.15) 46.1,44.4 46.1,46.775 45.075,47.8 v1(45.075,48.25) ; v1(55.765,43.905) 55.863,43.905 56.1,44.142 56.142,44.142 56.3,44.3 56.3,46.24 v1(56.294,46.246)
  Bottom Layer w0.1: v1(45.075,48.25) 46.625,46.7 49.825,46.7 50.857,45.668 50.874,45.668 50.891,45.65 51.873,45.65 52.469,46.246 v1(56.294,46.246)
BOARD_ID_WP: R909.2 U900.F13 U901.7 | length 20.1
  Top Layer w0.1: v1(44.975,41.4) 45.1,41.4 U900.F13@45.5,41 ; U901.7@55.6,47.45 56.009,47.45 56.199,47.64 v1(56.256,47.64) 56.35,47.64 56.69,47.3 R909.2@56.7,47.3
  Signal Layer 3 w0.1: v1(44.975,41.4) 46.275,42.7 46.275,43 46.9,43.625 46.9,47.325 v1(46.275,47.95) v1@46.275,48
  Signal Layer 4 w0.1: v1@46.275,48 46.29,48 46.64,48.35 55.546,48.35 v1(56.256,47.64)
BOARD_VER0: R930.1 U900.M5 | length 10.7
  Top Layer w0.1: v1(47.55,42.375) 48,42.825 48,43.149 48.101,43.25 48.104,43.25 48.249,43.396 48.249,43.466 48.25,43.467 48.25,43.65 48.35,43.75 49.25,43.75 U900.M5@49.5,44 ; R930.1@50.15,46.5 50.15,46.51 50.747,47.107 50.747,47.268 v1(50.825,47.346)
  Signal Layer 3 w0.1: v1(47.55,42.375) 48.025,42.85 48.025,43.375 49.061,44.411 49.061,46.149 50.258,47.346 v1(50.825,47.346)
BOARD_VER1: R931.1 U900.M6 | length 3
  Top Layer w0.1: U900.M6@49,44 48.75,44.25 48.75,44.661 49.149,45.06 49.149,46.099 49.43,46.38 49.44,46.38 49.579,46.519 R931.1@49.579,46.529
BREAKOUT_BOT4: J101.4 P101.10 U1.59 | length 123.3
  Top Layer w0.1: J101.4@38.55,2.962 J101.4@38.6,3.012 ; v1(80.438,39.217) 80.874,39.217 81.129,38.962 83.847,38.962 85.283,37.525 85.55,37.525 86,37.075 U1.59@86,36.75 ; v1(101.285,28.747) 101.302,28.73 P101.10@104.57,28.73
  Signal Layer 3 w0.1: v1(100.736,37.922) 100.988,37.671 100.988,37.217 101.478,36.727 101.478,31.536 101.285,31.344 v1(101.285,28.747)
  Signal Layer 4 w0.1: J101.4@38.57,3.262 38.57,8.776 46.995,17.201 69.53,17.201 80.506,28.176 81.059,28.176 81.179,28.297 87.694,28.297 87.873,28.118 91.824,28.118 92.764,29.058 92.764,30.864 92.768,30.868 95.033,33.133 97.449,33.133 97.775,33.133 99.302,33.133 101.285,31.151 v1(101.285,28.747) ; v1(80.438,39.217) 81.025,38.63 83.776,38.63 84.103,38.303 100.356,38.303 v1(100.736,37.922)
BREAKOUT_BOT5: J101.5 P101.8 U1.60 | length 119.5
  Top Layer w0.1: J101.5@41.05,2.962 J101.5@41.1,3.012 ; v1(79.694,38.955) 80.059,38.955 80.252,38.762 83.764,38.762 85.201,37.325 85.35,37.325 85.6,37.075 U1.60@85.6,36.75 ; v1(101.475,26.458) 101.479,26.458 101.724,26.213 104.547,26.213 P101.8@104.57,26.19
  Signal Layer 3 w0.1: v1(101.473,37.287) 101.473,37.177 101.678,36.972 101.678,28.584 101.475,28.381 v1(101.475,26.458)
  Signal Layer 4 w0.1: J101.5@41.11,3.262 41.11,10.655 47.32,16.866 61.239,16.866 61.747,16.358 69.799,16.358 78.966,25.524 79.962,25.524 80.34,25.146 84.252,25.146 85.682,26.576 86,26.576 86.299,26.277 87.259,26.277 87.919,26.937 99.021,26.937 99.5,26.458 v1(101.475,26.458) ; v1(79.694,38.955) 79.694,38.923 80.187,38.43 83.693,38.43 84.02,38.103 98.778,38.103 99.263,37.617 100.15,37.617 100.48,37.287 v1(101.473,37.287)
BREAKOUT_BOT6: J101.6 P101.13 R107.2 U1.18 | length 105.1
  Top Layer w0.1: J101.6@43.55,2.962 J101.6@43.6,3.012 ; v1(63.322,11.989) R107.2@63.322,12.678 ; v1(79.324,24.892) 79.324,27.686 80.213,28.575 82.354,28.575 82.4,28.621 U1.18@82.4,28.85 ; v1(106.629,32.614) 106.629,32.639 107.8,33.81 P101.13@108.76,33.81
  Signal Layer 3 w0.1: v1(62.887,6.751) 63.322,7.186 v1(63.322,11.989) ; v1(78.383,22.049) 78.789,22.049 79.096,21.742 79.908,21.742 80.324,22.158 80.324,22.97 79.324,23.97 v1(79.324,24.892)
  Signal Layer 4 w0.1: J101.6@43.65,3.262 46.481,6.093 57.706,6.093 58.364,6.751 74.67,6.751 77.114,9.195 77.114,11.481 75.52,13.076 75.52,19.186 v1(78.383,22.049) ; v1(79.324,24.892) 79.76,24.892 79.935,24.717 85.683,24.717 87.043,26.077 87.342,26.077 88.002,26.737 98.894,26.737 99.747,25.885 101.933,25.885 103.835,27.788 106.02,27.788 106.629,28.397 v1(106.629,32.614)
BREAKOUT_BOT7: J101.7 R106.2 U1.17 | length 61.8
  Top Layer w0.1: J101.7@46.15,2.962 J101.7@46.2,3.012 ; v1@66.7,12.04 R106.2@66.7,12.7 ; v1(80.775,29.304) 80.775,29.414 80.781,29.414 80.967,29.6 U1.17@81.65,29.6
  Signal Layer 3 w0.1: J101.7@46.19,3.262 47.422,4.494 47.422,17.667 v1(48.057,18.302) ; v1(66.7,12.04) 66.7,17.501 67.056,17.856 v1(67.056,18.669)
  Signal Layer 4 w0.1: v1(48.057,18.302) 48.934,18.302 49.127,18.494 65.862,18.494 66.037,18.669 v1(67.056,18.669) 67.923,18.669 68.097,18.494 69.693,18.494 80.174,28.976 80.447,28.976 v1(80.775,29.304)
BREAKOUT_BOT8: J101.8 P101.7 R323.2 | length 79.4
  Top Layer w0.1: J101.8@48.73,3.262 48.73,5.73 R323.2@48.75,5.75 49.336,5.75 v1(50.089,6.502) ; v1(106.68,24.994) 107.876,26.19 P101.7@108.76,26.19
  Signal Layer 4 w0.1: v1(50.089,6.502) 50.14,6.452 56.21,6.452 57.263,7.505 74.612,7.505 76.581,9.474 76.581,11.376 75.12,12.837 75.12,19.643 79.074,23.597 80.213,23.597 80.594,23.216 88.062,23.216 89.179,24.333 100.745,24.333 101.405,24.994 v1(106.68,24.994)
BREAKOUT_BOT9: J101.9 R317.2 | length 2.6
  Top Layer w0.1: J101.9@51.25,3.162 J101.9@51.3,3.212 ; J101.9@51.27,3.262 51.27,5.72 R317.2@51.3,5.75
